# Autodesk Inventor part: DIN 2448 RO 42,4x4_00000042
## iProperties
Created: 2006-02
Part Number: DIN 2448 RO 42,4x4_00000042
Material: Default
Document SubType Name: Modeling
Designer: FranzK
Stock Number: DIN 2448 RO 42,4x4
Mass: 75.7986 g
Surface Area: 388.644 cm^2
Volume: 75.7986 cm^3
Density: 1 g/cm^3
G_L: 157.080 mm
G_W: 42.400 mm
G_H: 42.400 mm
AFG_Item: 42.4 x 4
CSToolsMass: 0.1
CSToolsVolume: 75799.0
CSToolsArea: 389.0
Author: FranzK
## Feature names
1. AFG_Detailed_DIN 2448 RO 42,4x4_00000042
2. AFG_Simplified_DIN 2448 RO 42,4x4_00000042
